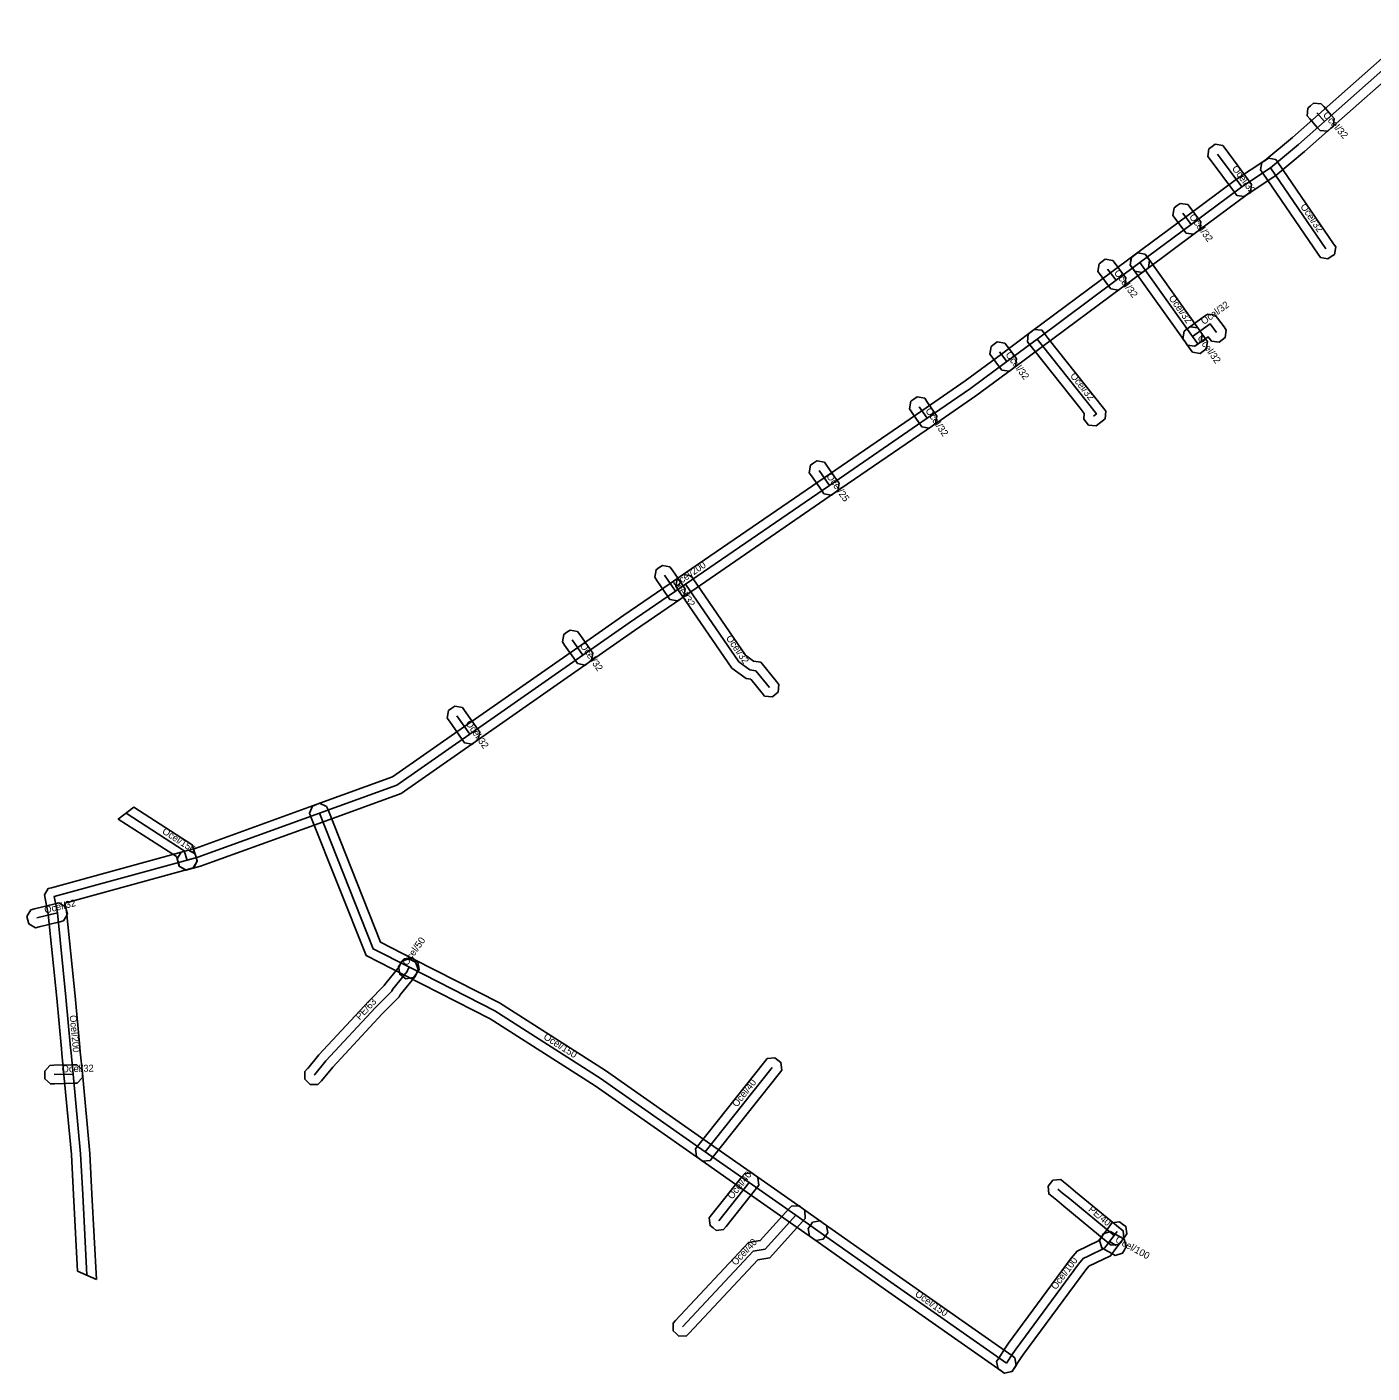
# Model space of a CAD drawing. Extents: x -600607 to -600238, y -1203924 to -1203617.
# Drawn here: x -600606.8 to -600461.6, y -1203842.3 to -1203697 of the extents above; entities that cross this region are included whole.
import ezdxf

# ---------------------------------------------------------------- set-up
doc = ezdxf.new("R2010")
doc.units = 0
for name, color, linetype in [('1', 7, 'Continuous'), ('14', 7, 'Continuous'), ('18', 7, 'Continuous'), ('20', 7, 'Continuous')]:
    doc.layers.add(name, color=color, linetype=linetype)

msp = doc.modelspace()

# ---------------------------------------------------------------- linework, layer by layer
at = {"layer": '1'}
msp.add_lwpolyline([(-600457.88, -1203700.73), (-600466.09, -1203708.01), (-600468.9, -1203710.5), (-600471.99, -1203713.06), (-600475.1, -1203715.11), (-600480.54, -1203719.16), (-600486.08, -1203723.28), (-600486.42, -1203723.53), (-600487.23, -1203723.41), (-600487.48, -1203723.08), (-600487.73, -1203722.74), (-600487.61, -1203721.93), (-600487.28, -1203721.68), (-600481.74, -1203717.56), (-600476.24, -1203713.47), (-600473.19, -1203711.46), (-600470.2, -1203708.98), (-600467.41, -1203706.51), (-600459.26, -1203699.29)], dxfattribs=at)
for points in [[(-600467.11, -1203705.33), (-600466.84, -1203705.64), (-600466, -1203706.6), (-600465.72, -1203706.91), (-600465.78, -1203707.74), (-600466.09, -1203708.01), (-600466.4, -1203708.29), (-600467.23, -1203708.23), (-600467.5, -1203707.92), (-600468.34, -1203706.96), (-600468.62, -1203706.65), (-600468.56, -1203705.82), (-600468.25, -1203705.55), (-600467.94, -1203705.27)], [(-600477.73, -1203709.83), (-600477.49, -1203710.16), (-600474.87, -1203713.69), (-600474.62, -1203714.03), (-600474.74, -1203714.85), (-600475.07, -1203715.09), (-600475.41, -1203715.34), (-600476.23, -1203715.22), (-600476.47, -1203714.89), (-600479.09, -1203711.36), (-600479.34, -1203711.02), (-600479.22, -1203710.2), (-600478.89, -1203709.96), (-600478.55, -1203709.71)], [(-600472, -1203711.35), (-600471.77, -1203711.7), (-600465.78, -1203720.44), (-600465.54, -1203720.78), (-600465.69, -1203721.59), (-600466.04, -1203721.82), (-600466.38, -1203722.06), (-600467.19, -1203721.91), (-600467.43, -1203721.56), (-600473.42, -1203712.82), (-600473.65, -1203712.48), (-600473.5, -1203711.67), (-600473.16, -1203711.44), (-600472.81, -1203711.2)], [(-600481.51, -1203716.2), (-600481.26, -1203716.53), (-600480.34, -1203717.76), (-600480.09, -1203718.09), (-600480.21, -1203718.91), (-600480.54, -1203719.16), (-600480.87, -1203719.41), (-600481.69, -1203719.29), (-600481.94, -1203718.96), (-600482.86, -1203717.73), (-600483.11, -1203717.4), (-600482.99, -1203716.58), (-600482.66, -1203716.33), (-600482.33, -1203716.08)], [(-600485.75, -1203723.04), (-600486.08, -1203723.28), (-600488.65, -1203725.19), (-600497.18, -1203731.53), (-600500.43, -1203733.95), (-600504.37, -1203736.87), (-600509.07, -1203740.1), (-600519.63, -1203747.34), (-600535.15, -1203758), (-600536.24, -1203758.75), (-600541.23, -1203762.17), (-600546.22, -1203765.67), (-600558.43, -1203774.2), (-600566.42, -1203779.78), (-600574.9, -1203782.85), (-600588.06, -1203787.6), (-600589.25, -1203787.93), (-600589.65, -1203788.03), (-600590.37, -1203787.62), (-600590.48, -1203787.22), (-600590.58, -1203786.82), (-600590.17, -1203786.1), (-600589.77, -1203785.99), (-600588.66, -1203785.7), (-600575.58, -1203780.97), (-600567.34, -1203777.99), (-600559.57, -1203772.56), (-600547.36, -1203764.03), (-600542.37, -1203760.53), (-600537.38, -1203757.11), (-600536.29, -1203756.36), (-600520.77, -1203745.7), (-600510.21, -1203738.46), (-600505.53, -1203735.25), (-600501.63, -1203732.35), (-600498.38, -1203729.93), (-600489.85, -1203723.59), (-600487.28, -1203721.68), (-600486.94, -1203721.43), (-600486.12, -1203721.55), (-600485.88, -1203721.88), (-600485.63, -1203722.22)], [(-600489.61, -1203722.24), (-600489.36, -1203722.57), (-600488.45, -1203723.79), (-600488.2, -1203724.12), (-600488.32, -1203724.94), (-600488.65, -1203725.19), (-600488.98, -1203725.44), (-600489.8, -1203725.32), (-600490.05, -1203724.99), (-600490.96, -1203723.77), (-600491.21, -1203723.44), (-600491.09, -1203722.62), (-600490.76, -1203722.37), (-600490.43, -1203722.12)], [(-600486.11, -1203721.56), (-600485.87, -1203721.9), (-600480.18, -1203729.87), (-600479.94, -1203730.21), (-600480.07, -1203731.02), (-600480.41, -1203731.26), (-600480.75, -1203731.51), (-600481.56, -1203731.37), (-600481.8, -1203731.03), (-600487.49, -1203723.06), (-600487.73, -1203722.72), (-600487.6, -1203721.91), (-600487.26, -1203721.67), (-600486.92, -1203721.43)], [(-600478.95, -1203730.95), (-600479.2, -1203730.62), (-600479.31, -1203730.47), (-600480.4, -1203731.26), (-600480.74, -1203731.5), (-600481.56, -1203731.37), (-600481.8, -1203731.04), (-600482.04, -1203730.7), (-600481.91, -1203729.88), (-600481.58, -1203729.64), (-600479.69, -1203728.27), (-600479.35, -1203728.03), (-600478.54, -1203728.15), (-600478.3, -1203728.48), (-600477.6, -1203729.42), (-600477.35, -1203729.76), (-600477.47, -1203730.57), (-600477.8, -1203730.82), (-600478.14, -1203731.07)], [(-600480.42, -1203729.53), (-600480.18, -1203729.87), (-600479.62, -1203730.65), (-600479.38, -1203730.98), (-600479.51, -1203731.8), (-600479.85, -1203732.04), (-600480.18, -1203732.28), (-600481, -1203732.15), (-600481.24, -1203731.81), (-600481.8, -1203731.03), (-600482.04, -1203730.7), (-600481.91, -1203729.88), (-600481.57, -1203729.64), (-600481.24, -1203729.4)], [(-600492.74, -1203739.37), (-600492.68, -1203738.77), (-600493.13, -1203738.19), (-600498.13, -1203731.89), (-600498.56, -1203731.35), (-600498.82, -1203731.03), (-600498.73, -1203730.21), (-600498.4, -1203729.95), (-600498.08, -1203729.69), (-600497.26, -1203729.78), (-600497, -1203730.11), (-600496.57, -1203730.65), (-600491.57, -1203736.95), (-600490.59, -1203738.18), (-600490.34, -1203738.5), (-600490.43, -1203739.32), (-600490.75, -1203739.58), (-600491.07, -1203739.84), (-600491.39, -1203740.1), (-600492.21, -1203740.01), (-600492.48, -1203739.69)], [(-600501.27, -1203731.16), (-600501.02, -1203731.49), (-600500.23, -1203732.55), (-600499.98, -1203732.88), (-600500.1, -1203733.7), (-600500.43, -1203733.95), (-600500.76, -1203734.2), (-600501.58, -1203734.08), (-600501.83, -1203733.75), (-600502.62, -1203732.69), (-600502.87, -1203732.36), (-600502.75, -1203731.54), (-600502.42, -1203731.29), (-600502.09, -1203731.04)], [(-600509.91, -1203737.12), (-600509.68, -1203737.46), (-600508.82, -1203738.71), (-600508.58, -1203739.05), (-600508.73, -1203739.87), (-600509.07, -1203740.1), (-600509.41, -1203740.34), (-600510.23, -1203740.19), (-600510.46, -1203739.85), (-600511.32, -1203738.6), (-600511.56, -1203738.26), (-600511.41, -1203737.44), (-600511.07, -1203737.21), (-600510.73, -1203736.97)], [(-600520.72, -1203744.01), (-600520.49, -1203744.35), (-600519.38, -1203745.95), (-600519.14, -1203746.29), (-600519.29, -1203747.11), (-600519.63, -1203747.34), (-600519.97, -1203747.58), (-600520.79, -1203747.43), (-600521.02, -1203747.09), (-600522.13, -1203745.49), (-600522.37, -1203745.15), (-600522.22, -1203744.33), (-600521.88, -1203744.1), (-600521.54, -1203743.86)], [(-600537.4, -1203755.3), (-600537.17, -1203755.64), (-600535.98, -1203757.36), (-600535.75, -1203757.71), (-600535.9, -1203758.52), (-600536.24, -1203758.76), (-600536.59, -1203758.99), (-600537.4, -1203758.84), (-600537.64, -1203758.5), (-600538.82, -1203756.78), (-600539.05, -1203756.43), (-600538.9, -1203755.62), (-600538.56, -1203755.39), (-600538.21, -1203755.15)], [(-600535.13, -1203756.27), (-600534.9, -1203756.61), (-600529.25, -1203764.84), (-600528.37, -1203765.48), (-600527.61, -1203765.61), (-600525.9, -1203767.68), (-600525.64, -1203768), (-600525.71, -1203768.83), (-600526.03, -1203769.09), (-600526.35, -1203769.35), (-600527.18, -1203769.28), (-600527.44, -1203768.96), (-600528.69, -1203767.45), (-600529.17, -1203767.36), (-600530.71, -1203766.26), (-600536.55, -1203757.75), (-600536.78, -1203757.4), (-600536.63, -1203756.59), (-600536.29, -1203756.35), (-600535.94, -1203756.12)], [(-600547.37, -1203762.28), (-600547.13, -1203762.62), (-600545.97, -1203764.28), (-600545.73, -1203764.62), (-600545.88, -1203765.43), (-600546.22, -1203765.67), (-600546.56, -1203765.91), (-600547.37, -1203765.76), (-600547.61, -1203765.42), (-600548.77, -1203763.76), (-600549.01, -1203763.42), (-600548.86, -1203762.61), (-600548.52, -1203762.37), (-600548.18, -1203762.13)], [(-600559.81, -1203770.49), (-600559.57, -1203770.82), (-600558.18, -1203772.8), (-600557.94, -1203773.14), (-600558.09, -1203773.96), (-600558.43, -1203774.2), (-600558.76, -1203774.44), (-600559.58, -1203774.29), (-600559.82, -1203773.96), (-600561.21, -1203771.98), (-600561.45, -1203771.64), (-600561.3, -1203770.82), (-600560.96, -1203770.58), (-600560.63, -1203770.34)], [(-600590.68, -1203786.59), (-600596.96, -1203782.53), (-600595.26, -1203781.25), (-600588.98, -1203785.31), (-600588.56, -1203786.66), (-600588.43, -1203787.05), (-600588.81, -1203787.79), (-600589.21, -1203787.91), (-600589.6, -1203788.04), (-600590.34, -1203787.66), (-600590.46, -1203787.26)], [(-600574.46, -1203781.16), (-600574.31, -1203781.54), (-600568.63, -1203795.83), (-600565.07, -1203797.64), (-600555.8, -1203802.36), (-600544.36, -1203809.67), (-600533.03, -1203817.61), (-600528.28, -1203820.94), (-600523.25, -1203824.46), (-600520.85, -1203826.14), (-600520.52, -1203826.38), (-600520.37, -1203827.2), (-600520.61, -1203827.53), (-600520.85, -1203827.87), (-600521.67, -1203828.02), (-600522.01, -1203827.78), (-600524.39, -1203826.1), (-600529.42, -1203822.58), (-600534.17, -1203819.25), (-600545.48, -1203811.33), (-600556.8, -1203804.1), (-600565.97, -1203799.42), (-600570.21, -1203797.27), (-600576.17, -1203782.28), (-600576.32, -1203781.89), (-600575.99, -1203781.13), (-600575.61, -1203780.98), (-600575.22, -1203780.83)], [(-600599.31, -1203832.21), (-600601.35, -1203831.32), (-600601.79, -1203823.1), (-600602.01, -1203818.75), (-600602.82, -1203810.15), (-600603.04, -1203807.85), (-600603.09, -1203807.32), (-600603.59, -1203801.85), (-600604.5, -1203792.8), (-600604.85, -1203791.1), (-600604.93, -1203790.71), (-600604.52, -1203790.04), (-600604.14, -1203789.94), (-600589.78, -1203786), (-600589.38, -1203785.89), (-600588.66, -1203786.3), (-600588.55, -1203786.7), (-600588.44, -1203787.09), (-600588.85, -1203787.81), (-600589.24, -1203787.92), (-600602.7, -1203791.62), (-600602.52, -1203792.5), (-600601.6, -1203801.65), (-600601.09, -1203807.14), (-600601.05, -1203807.67), (-600600.82, -1203809.96), (-600600.01, -1203818.61), (-600599.79, -1203823)], [(-600606.38, -1203792.33), (-600605.98, -1203792.23), (-600603.75, -1203791.68), (-600603.35, -1203791.58), (-600602.64, -1203792.01), (-600602.54, -1203792.41), (-600602.44, -1203792.81), (-600602.87, -1203793.52), (-600603.27, -1203793.62), (-600605.5, -1203794.17), (-600605.9, -1203794.27), (-600606.61, -1203793.84), (-600606.71, -1203793.44), (-600606.81, -1203793.04)], [(-600576.82, -1203809.77), (-600576.53, -1203809.47), (-600576.49, -1203809.44), (-600575.29, -1203807.98), (-600569.91, -1203802.19), (-600568.25, -1203800.49), (-600568.18, -1203800.38), (-600566.64, -1203798.47), (-600566.56, -1203798.3), (-600566.39, -1203797.92), (-600565.62, -1203797.63), (-600565.24, -1203797.8), (-600564.86, -1203797.97), (-600564.57, -1203798.74), (-600564.74, -1203799.12), (-600564.92, -1203799.53), (-600566.52, -1203801.5), (-600566.63, -1203801.71), (-600568.47, -1203803.57), (-600573.79, -1203809.3), (-600575.01, -1203810.78), (-600575.11, -1203810.89), (-600575.41, -1203811.18), (-600576.23, -1203811.18), (-600576.53, -1203810.89), (-600576.82, -1203810.59)], [(-600566.7, -1203798.46), (-600566.46, -1203798.12), (-600566.33, -1203797.95), (-600566.09, -1203797.61), (-600565.27, -1203797.48), (-600564.94, -1203797.72), (-600564.6, -1203797.96), (-600564.47, -1203798.78), (-600564.71, -1203799.11), (-600564.84, -1203799.29), (-600565.08, -1203799.63), (-600565.9, -1203799.76), (-600566.23, -1203799.52), (-600566.57, -1203799.28)], [(-600601.38, -1203811.04), (-600601.79, -1203811.05), (-600603.85, -1203811.11), (-600604.27, -1203811.12), (-600604.87, -1203810.55), (-600604.88, -1203810.14), (-600604.89, -1203809.73), (-600604.32, -1203809.12), (-600603.91, -1203809.11), (-600601.85, -1203809.05), (-600601.44, -1203809.04), (-600600.83, -1203809.61), (-600600.82, -1203810.02), (-600600.81, -1203810.44)], [(-600534.64, -1203818.13), (-600534.38, -1203817.81), (-600527.15, -1203808.71), (-600526.9, -1203808.38), (-600526.07, -1203808.29), (-600525.75, -1203808.55), (-600525.42, -1203808.8), (-600525.33, -1203809.63), (-600525.59, -1203809.95), (-600532.82, -1203819.05), (-600533.08, -1203819.38), (-600533.9, -1203819.47), (-600534.22, -1203819.21), (-600534.55, -1203818.96)], [(-600527.81, -1203822.06), (-600528.07, -1203822.38), (-600531.35, -1203826.5), (-600531.61, -1203826.83), (-600532.43, -1203826.92), (-600532.75, -1203826.66), (-600533.08, -1203826.4), (-600533.17, -1203825.58), (-600532.91, -1203825.26), (-600529.63, -1203821.14), (-600529.37, -1203820.81), (-600528.55, -1203820.72), (-600528.23, -1203820.98), (-600527.9, -1203821.24)], [(-600495.23, -1203821.44), (-600494.91, -1203821.7), (-600494.4, -1203822.13), (-600493.62, -1203822.76), (-600488.82, -1203826.71), (-600488.5, -1203826.97), (-600488.43, -1203827.8), (-600488.69, -1203828.12), (-600488.95, -1203828.44), (-600489.78, -1203828.52), (-600490.1, -1203828.25), (-600494.88, -1203824.3), (-600495.66, -1203823.67), (-600496.19, -1203823.24), (-600496.51, -1203822.98), (-600496.58, -1203822.15), (-600496.32, -1203821.83), (-600496.06, -1203821.51)], [(-600537.07, -1203836.95), (-600536.79, -1203836.65), (-600528.91, -1203828.23), (-600527.65, -1203828.02), (-600524.56, -1203824.61), (-600524.28, -1203824.3), (-600523.46, -1203824.26), (-600523.15, -1203824.54), (-600522.84, -1203824.82), (-600522.8, -1203825.64), (-600523.08, -1203825.95), (-600526.63, -1203829.88), (-600527.91, -1203830.09), (-600535.33, -1203838.01), (-600535.61, -1203838.31), (-600536.44, -1203838.34), (-600536.74, -1203838.06), (-600537.05, -1203837.78)], [(-600521.19, -1203825.9), (-600520.85, -1203826.14), (-600512.97, -1203831.69), (-600500.51, -1203840.44), (-600500.17, -1203840.68), (-600500.02, -1203841.5), (-600500.26, -1203841.83), (-600500.5, -1203842.17), (-600501.32, -1203842.32), (-600501.65, -1203842.08), (-600514.12, -1203833.33), (-600522.01, -1203827.78), (-600522.34, -1203827.54), (-600522.49, -1203826.72), (-600522.25, -1203826.38), (-600522.01, -1203826.05)], [(-600502.14, -1203841.06), (-600501.92, -1203840.71), (-600501.23, -1203839.65), (-600500.87, -1203839.11), (-600494.1, -1203829.94), (-600493.45, -1203829.16), (-600491.15, -1203828.06), (-600490.76, -1203827.54), (-600490.26, -1203826.88), (-600489.94, -1203826.45), (-600489.7, -1203826.12), (-600488.88, -1203826), (-600488.54, -1203826.25), (-600488.21, -1203826.5), (-600488.09, -1203827.31), (-600488.34, -1203827.65), (-600488.66, -1203828.08), (-600489.16, -1203828.74), (-600489.85, -1203829.66), (-600492.19, -1203830.78), (-600492.52, -1203831.18), (-600499.23, -1203840.27), (-600499.56, -1203840.75), (-600500.24, -1203841.81), (-600500.47, -1203842.15), (-600501.28, -1203842.32), (-600501.63, -1203842.1), (-600501.97, -1203841.87)], [(-600489.84, -1203827.06), (-600489.48, -1203827.26), (-600488.75, -1203827.66), (-600488.39, -1203827.86), (-600488.15, -1203828.66), (-600488.35, -1203829.02), (-600488.55, -1203829.38), (-600489.35, -1203829.62), (-600489.71, -1203829.42), (-600490.44, -1203829.02), (-600490.8, -1203828.82), (-600491.04, -1203828.02), (-600490.84, -1203827.66), (-600490.64, -1203827.3)]]:
    msp.add_lwpolyline(points, close=True, dxfattribs=at)
at = {"layer": '14'}
for points in [[(-600376.52, -1203617.62), (-600381.81, -1203622.65), (-600388.25, -1203628.77), (-600399.65, -1203639.6), (-600410.04, -1203649.48), (-600410.35, -1203649.77), (-600417.47, -1203657.21), (-600420.27, -1203660.14), (-600432.74, -1203673.17), (-600439.94, -1203680.7), (-600445.87, -1203686.85), (-600458.57, -1203700.01), (-600466.75, -1203707.26), (-600469.55, -1203709.74), (-600472.59, -1203712.26), (-600475.67, -1203714.29), (-600481.14, -1203718.36), (-600486.68, -1203722.48)], [(-600467.59, -1203706.3), (-600466.75, -1203707.26)], [(-600478.29, -1203710.76), (-600475.67, -1203714.29)], [(-600472.59, -1203712.26), (-600466.6, -1203721)], [(-600482.06, -1203717.13), (-600481.14, -1203718.36)], [(-600486.68, -1203722.48), (-600489.25, -1203724.39), (-600497.78, -1203730.73), (-600501.03, -1203733.15), (-600504.95, -1203736.06), (-600509.64, -1203739.28), (-600520.2, -1203746.52), (-600535.72, -1203757.18), (-600536.81, -1203757.93), (-600541.8, -1203761.35), (-600546.79, -1203764.85), (-600559, -1203773.38), (-600566.88, -1203778.88), (-600575.24, -1203781.91), (-600588.36, -1203786.65), (-600589.51, -1203786.96)], [(-600490.16, -1203723.17), (-600489.25, -1203724.39)], [(-600486.68, -1203722.48), (-600480.99, -1203730.45)], [(-600478.4, -1203730.02), (-600479.1, -1203729.08), (-600480.99, -1203730.45)], [(-600497.78, -1203730.73), (-600497.35, -1203731.27), (-600492.35, -1203737.57), (-600491.38, -1203738.8), (-600491.7, -1203739.06)], [(-600480.99, -1203730.45), (-600480.43, -1203731.23)], [(-600501.82, -1203732.09), (-600501.03, -1203733.15)], [(-600510.5, -1203738.03), (-600509.64, -1203739.28)], [(-600521.31, -1203744.92), (-600520.2, -1203746.52)], [(-600537.99, -1203756.21), (-600536.81, -1203757.93)], [(-600535.72, -1203757.18), (-600529.98, -1203765.55), (-600528.77, -1203766.42), (-600528.15, -1203766.53), (-600526.67, -1203768.32)], [(-600547.95, -1203763.19), (-600546.79, -1203764.85)], [(-600560.39, -1203771.4), (-600559, -1203773.38)], [(-600596.11, -1203781.89), (-600589.83, -1203785.95), (-600589.51, -1203786.96)], [(-600575.24, -1203781.91), (-600569.42, -1203796.55), (-600565.52, -1203798.53), (-600556.3, -1203803.23), (-600544.92, -1203810.5), (-600533.6, -1203818.43), (-600528.85, -1203821.76), (-600523.82, -1203825.28), (-600521.43, -1203826.96)], [(-600589.51, -1203786.96), (-600603.87, -1203790.9), (-600603.51, -1203792.65), (-600602.6, -1203801.75), (-600602.09, -1203807.23), (-600602.04, -1203807.76), (-600601.82, -1203810.05), (-600601.01, -1203818.68), (-600600.79, -1203823.05), (-600600.33, -1203831.77)], [(-600605.74, -1203793.2), (-600603.51, -1203792.65)], [(-600575.82, -1203810.18), (-600575.75, -1203810.11), (-600574.54, -1203808.64), (-600569.19, -1203802.88), (-600569.18, -1203802.87), (-600567.44, -1203801.1), (-600567.35, -1203800.94), (-600565.78, -1203799), (-600565.65, -1203798.71)], [(-600565.65, -1203798.71), (-600565.52, -1203798.53)], [(-600495.55, -1203822.47), (-600495.03, -1203822.9), (-600494.25, -1203823.53), (-600489.46, -1203827.48)], [(-600536.06, -1203837.33), (-600528.41, -1203829.16), (-600527.14, -1203828.95), (-600523.82, -1203825.28)], [(-600521.43, -1203826.96), (-600513.55, -1203832.51), (-600501.08, -1203841.26)], [(-600501.08, -1203841.26), (-600500.39, -1203840.2), (-600500.05, -1203839.69), (-600493.31, -1203830.56), (-600492.82, -1203829.97), (-600492.28, -1203829.71), (-600490.5, -1203828.86), (-600489.96, -1203828.14), (-600489.46, -1203827.48), (-600489.14, -1203827.05)]]:
    msp.add_lwpolyline(points, dxfattribs=at)
at = {"layer": '18'}
for points in [[(-600601.82, -1203810.05), (-600603.88, -1203810.11)], [(-600533.6, -1203818.43), (-600526.37, -1203809.33)], [(-600528.85, -1203821.76), (-600532.13, -1203825.88)], [(-600489.96, -1203828.14), (-600489.23, -1203828.54)]]:
    msp.add_lwpolyline(points, dxfattribs=at)

# ---------------------------------------------------------------- texts
at = {"layer": '20'}
for s, rotation, p in [('Ocel/32', 311.1859, (-600466.97, -1203706.58)), ('Ocel/32', 306.5832, (-600476.78, -1203712.33)), ('Ocel/32', 304.425, (-600469.4, -1203716.43)), ('Ocel/32', 306.7953, (-600481.4, -1203717.55)), ('Ocel/32', 306.7193, (-600489.51, -1203723.58)), ('Ocel/32', 305.5241, (-600483.61, -1203726.31)), ('Ocel/32', 35.9371, (-600479.77, -1203729.22)), ('Ocel/32', 305.6764, (-600480.51, -1203730.64)), ('Ocel/32', 306.6965, (-600501.23, -1203732.42)), ('Ocel/32', 308.4373, (-600494.25, -1203734.72)), ('Ocel/32', 304.528, (-600509.87, -1203738.46)), ('Ocel/25', 304.751, (-600520.56, -1203745.52)), ('Ocel/200', 34.5308, (-600536.75, -1203757.55)), ('Ocel/32', 304.4519, (-600537.2, -1203756.87)), ('Ocel/32', 304.4416, (-600531.39, -1203763)), ('Ocel/32', 304.9457, (-600547.17, -1203763.82)), ('Ocel/32', 305.0696, (-600559.5, -1203772.19)), ('Ocel/150', 327.1, (-600592.28, -1203784.03)), ('Ocel/32', 13.8547, (-600604.83, -1203792.73)), ('Ocel/50', 54.1623, (-600565.78, -1203798.42)), ('PE/63', 47.1135, (-600570.88, -1203804.28)), ('Ocel/200', 275.317, (-600602.2, -1203803.73)), ('Ocel/150', 327.4279, (-600551.12, -1203806.21)), ('Ocel/32', 1.6683, (-600603.05, -1203809.88)), ('Ocel/40', 51.5327, (-600530.18, -1203813.68)), ('Ocel/40', 51.4761, (-600530.69, -1203823.62)), ('PE/40', 320.4898, (-600492.3, -1203824.77)), ('Ocel/40', 46.8826, (-600530.3, -1203830.77)), ('Ocel/100', 331.2797, (-600489.4, -1203828.14)), ('Ocel/100', 53.5643, (-600495.74, -1203833.39)), ('Ocel/150', 324.9433, (-600511.02, -1203833.95))]:
    msp.add_text(s, height=0.75, rotation=rotation, dxfattribs=at).set_placement(p)

doc.saveas('drawing.dxf')
